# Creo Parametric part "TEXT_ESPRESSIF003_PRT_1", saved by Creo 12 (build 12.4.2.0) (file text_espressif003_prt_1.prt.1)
Units: Custom; MM, KILOGRAM, SECS

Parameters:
  PTC_WM_ITERATION = "0"
  PTC_WM_VERSION = "-.0"
  PTC_WM_LIFECYCLE_STATE = "In Work"
  PTC_WM_LIFECYCLE = "MO_CADDocument"
  PTC_WM_CREATED_BY = "Maximilian Roepper (Z0017RMS: MO)"
  PTC_WM_CREATED_ON = "18-Sep-26 11:36:42 AM"
  PTC_WM_MODIFIED_BY = "Maximilian Roepper (Z0017RMS: MO)"
  PTC_WM_MODIFIED_ON = "18-Sep-26 11:36:46 AM"
  PDMLINKNUMBER = "PDM000071455108"
  PTC_WM_NAME = "text_espressif003_prt_1.prt"
  PTC_WM_NUMBER = "PDM000071455108"

Other parameters: WEIGHT, WEIGHT_FACTOR, WEIGHT_ADD, _MASS_TEMP, _DIFF_TEMP, MC_ERRORS, SUPPLIER

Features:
  1. coordinate system
  2. datum plane "PRT_YZ"
  3. datum plane "PRT_XY"
  4. datum plane "PRT_XZ"
  5. coordinate system
  6. datum axis
  7. datum axis
  8. datum axis
  9. coordinate system
  10. imported feature
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
Other named items: PRT, SIEMENS_MO, DRW_VIEW_ORG, PRT_X, PRT_Y, PRT_Z, CS0, ROUGH_GROB

Layers: 00_STD_CSYS-KSYS, 01_STD_PLANES-EBENEN, 02_STD_AXES-ACHSEN, 03_STD_CSYS-KSYS, 24_IMPORT_FEAT-IMPORT_KE

Surfaces: 16 tabulated cylinder, 13 plane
